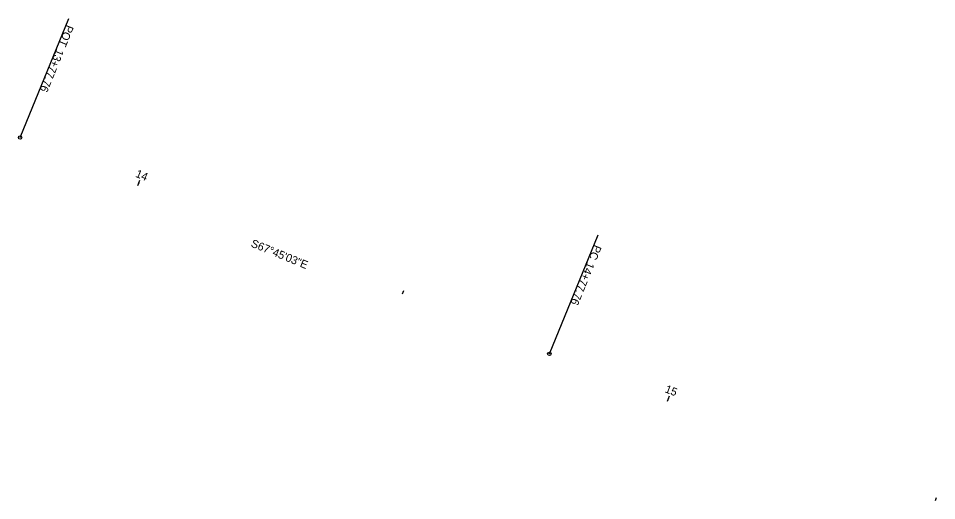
# Model space of a CAD drawing. Extents: x 2273904 to 2275373, y 654575 to 654883.
# Drawn here: x 2273904.4 to 2274065, y 654792.3 to 654876.6 of the extents above; entities that cross this region are included whole.
import ezdxf

# ---------------------------------------------------------------- set-up
doc = ezdxf.new("R2010")
doc.units = 0
for name, color, linetype in [('DR_P_Headwall', 7, 'Continuous'), ('DR_P_Storm_Sewer', 7, 'Continuous'), ('GE_X_Alignment_1000_Stations', 7, 'Continuous'), ('GE_X_Alignment_500_Stations', 7, 'Continuous'), ('PV_P_Drive', 7, 'Continuous')]:
    doc.layers.add(name, color=color, linetype=linetype)

msp = doc.modelspace()

# ---------------------------------------------------------------- linework, layer by layer
at = {"layer": 'DR_P_Storm_Sewer'}
for p, q in [((2273904.71, 654855.81), (2273913.23, 654876.64)), ((2273925.3, 654847.39), (2273925.53, 654847.95)), ((2273997.27, 654817.95), (2274005.79, 654838.77)), ((2274017.92, 654809.69), (2274018.28, 654810.62))]:
    msp.add_line(p, q, dxfattribs=at)
for centre in [(2273904.71, 654855.81), (2273997.27, 654817.95)]:
    msp.add_circle(centre, 0.3, dxfattribs=at)
at = {"layer": 'GE_X_Alignment_1000_Stations'}
for p, q in [((2273904.71, 654855.81), (2273913.23, 654876.64)), ((2273925.3, 654847.39), (2273925.68, 654848.32)), ((2273997.27, 654817.95), (2274005.79, 654838.77)), ((2273971.58, 654828.46), (2273971.81, 654829.02)), ((2274017.92, 654809.69), (2274018.28, 654810.62)), ((2274064.79, 654792.29), (2274064.99, 654792.86))]:
    msp.add_line(p, q, dxfattribs=at)
for centre in [(2273904.71, 654855.81), (2273997.27, 654817.95)]:
    msp.add_circle(centre, 0.3, dxfattribs=at)
at = {"layer": 'PV_P_Drive'}
for p, q in [((2273904.71, 654855.81), (2273913.23, 654876.64)), ((2273997.27, 654817.95), (2274005.79, 654838.77)), ((2274017.92, 654809.69), (2274018.14, 654810.25))]:
    msp.add_line(p, q, dxfattribs=at)
for centre in [(2273904.71, 654855.81), (2273997.27, 654817.95)]:
    msp.add_circle(centre, 0.3, dxfattribs=at)

# ---------------------------------------------------------------- texts
at = {"layer": 'DR_P_Headwall'}
msp.add_text('S67°45\'03"E', height=1.4, rotation=337.751, dxfattribs=at).set_placement((2273944.96, 654836.76))
at = {"layer": 'DR_P_Storm_Sewer'}
for s, rotation, p in [('POT', 247.751, (2273912.84, 654875.61)), ('13+77.76', 247.751, (2273911.11, 654871.38)), ('PC', 247.751, (2274005.15, 654837.14)), ('14+77.76', 247.751, (2274003.91, 654834.12)), ('15', 338.6404, (2274017.36, 654811.28))]:
    msp.add_text(s, height=1.4, rotation=rotation, dxfattribs=at).set_placement(p)
at = {"layer": 'GE_X_Alignment_1000_Stations'}
for s, rotation, p in [('POT', 247.751, (2273912.84, 654875.61)), ('13+77.76', 247.751, (2273911.11, 654871.38)), ('14', 337.751, (2273924.78, 654848.96)), ('PC', 247.751, (2274005.15, 654837.14)), ('14+77.76', 247.751, (2274003.91, 654834.12)), ('15', 338.6404, (2274017.36, 654811.28))]:
    msp.add_text(s, height=1.4, rotation=rotation, dxfattribs=at).set_placement(p)
at = {"layer": 'GE_X_Alignment_500_Stations'}
msp.add_text('S67°45\'03"E', height=1.4, rotation=337.751, dxfattribs=at).set_placement((2273944.96, 654836.76))
msp.add_text('S67°45\'03"E', height=1.4, rotation=337.751, dxfattribs=at).set_placement((2273944.96, 654836.76))
at = {"layer": 'PV_P_Drive'}
for s, p in [('POT', (2273912.84, 654875.61)), ('13+77.76', (2273911.11, 654871.38)), ('PC', (2274005.15, 654837.14)), ('14+77.76', (2274003.91, 654834.12))]:
    msp.add_text(s, height=1.4, rotation=247.751, dxfattribs=at).set_placement(p)

doc.saveas('drawing.dxf')
